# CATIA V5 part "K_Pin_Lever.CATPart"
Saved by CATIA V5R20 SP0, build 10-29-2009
Part number: Pin_Lever
Bounding box of the stored display mesh (mm): x -14.5 to 14.5, y 66.024 to 69.024, z -60.5 to -57.5
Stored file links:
  G:\Khaled_CFAO_2011\SIL\SIL_GR2\ctanaphiko\Khaled\CAD_ThinkMOTION\K_Pin_Lever.CATPart
  G:\Khaled_CFAO_2011\SIL\SIL_GR2\ctanaphiko\CATIA\ctanaphiko.CATProduct
  G:\Khaled_CFAO_2011\SIL\SIL_GR2\ctanaphiko\Khaled\CAD_ThinkMOTION\K_Part4.CATPart
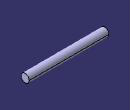
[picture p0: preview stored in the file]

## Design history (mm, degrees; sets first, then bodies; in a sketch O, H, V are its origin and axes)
External parameters (linked from other documents)
  External.Width_Leg_Support = 75 mm
AxisSystem1: origin (0, 0, 0), X (1, 0, 0), Y (0, 1, 0), Z (0, 0, 1)
Set1
  DatumCurve1: linked copy from another document
Body1 (main body)
  Sketch1 on yz-plane, origin (0, 0, 0), H (0, 1, 0), V (0, 0, 1)
    circle A1 centre (67.524, -59) radius 1.5
    reference projected arc E1 centre (67.524, -59) radius 1.5 from (67.524, -60.5) to (67.524, -57.5) ccw from edge of DatumCurve1
    radius A1 = 1.5
    concentricity: A1 E1
  Pad1: profile Sketch1, direction (1, 0, 0), length 14.5 {= External.Width_Leg_Support /6+2mm}, mirrored extent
